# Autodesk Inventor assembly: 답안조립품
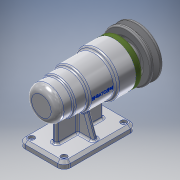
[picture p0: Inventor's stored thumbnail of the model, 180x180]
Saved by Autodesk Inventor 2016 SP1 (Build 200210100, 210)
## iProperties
Created: 2016-06
Part Number: 답안조립품
Material: 일반
Document SubType Name: Assembly
Designer: basic
Author: basic
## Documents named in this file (12)
- C:\Users\basic\Desktop\460608v1009\답안조립품.iam
- C:\Users\basic\Desktop\460608v1009\본체.ipt
- C:\Users\basic\Desktop\460608v1009\커버.ipt
- C:\Users\basic\Desktop\460608v1009\베어링 51202.ipt
- C:\Users\basic\Desktop\460608v1009\어댑터슬리브.ipt
- C:\Users\basic\Desktop\460608v1009\베어링 6004.ipt
- C:\Users\basic\Desktop\460608v1009\축.ipt
- C:\Users\basic\Desktop\460608v1009\키 5 x 5 x 16.ipt
- C:\Users\basic\Desktop\460608v1009\오일 실.ipt
- C:\Users\basic\Desktop\460608v1009\V벨트풀리.ipt
- C:\Users\basic\Desktop\460608v1009\멈춤나사 M3x8.ipt
- C:\Users\basic\Desktop\460608v1009\볼트 M4 x 12.ipt
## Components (5 placed, 2 different names)
1. V벨트풀리:2
2. ISO 4762 M4 x 12:1
3. ISO 4762 M4 x 12:2
4. ISO 4762 M4 x 12:3
5. ISO 4762 M4 x 12:4
